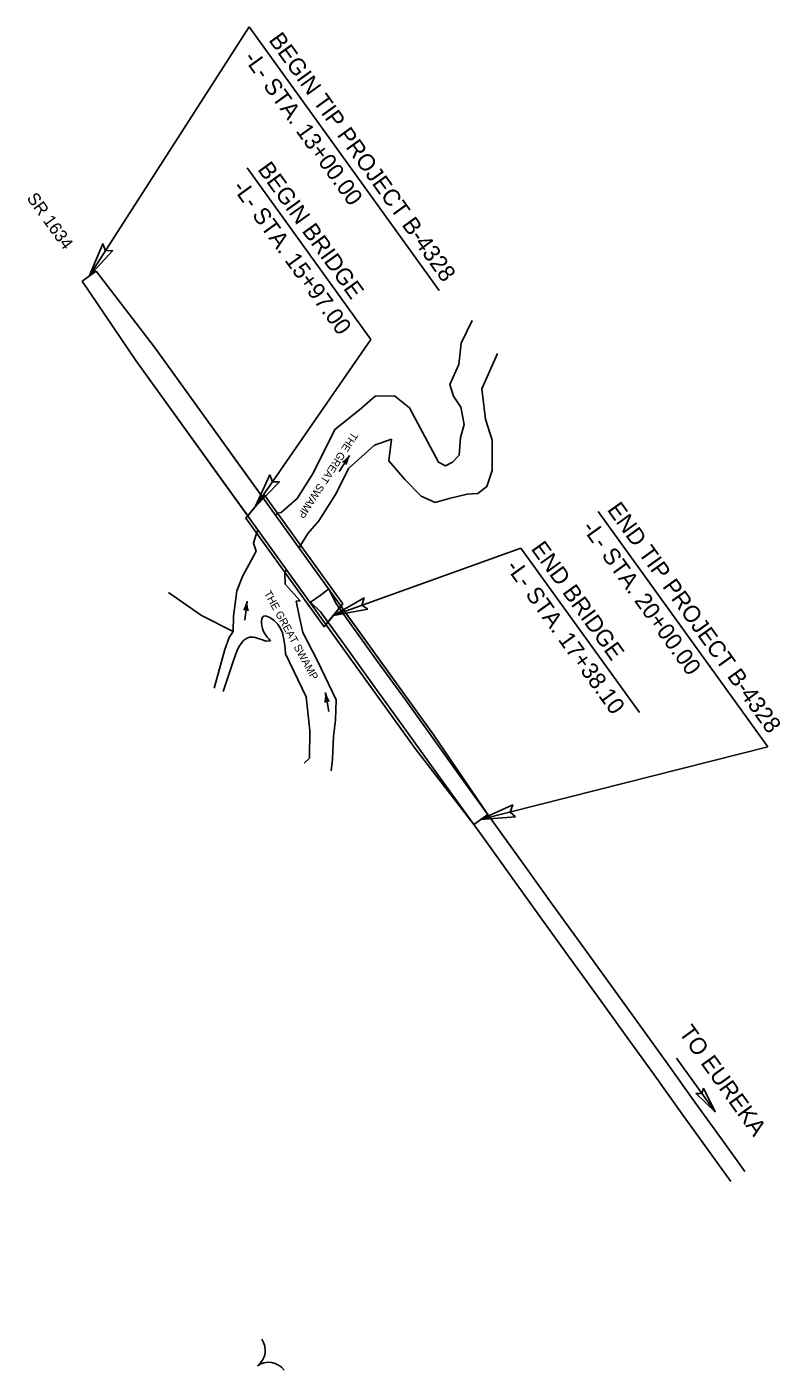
# Model space of a CAD drawing. Extents: x 1372027 to 1374286, y 553832 to 556743.
# Drawn here: x 1372027 to 1372814, y 553929 to 555333 of the extents above; entities that cross this region are included whole.
import ezdxf

# ---------------------------------------------------------------- set-up
doc = ezdxf.new("R2010")
doc.units = 0
for name, color, linetype in [('Default', 7, 'Continuous'), ('Old_Level_1', 7, 'Continuous'), ('Prop Dimension', 7, 'Continuous'), ('Prop EOT', 7, 'Continuous'), ('Prop Roadway Bridge', 7, 'Continuous'), ('Prop Shade Light', 7, 'Continuous'), ('Prop Shade Medium', 7, 'Continuous'), ('Prop Terminator CELL', 7, 'Continuous'), ('Sheet Plan Layout CELL', 7, 'Continuous')]:
    doc.layers.add(name, color=color, linetype=linetype)

# ---------------------------------------------------------------- blocks, each defined once
blk = doc.blocks.new('EXIST HYDRO RIVER FLOW ARROW')
at = {"layer": 'Default'}
for p, q in [((0.2, 0), (-0.2, 0)), ((0, 0.04575), (0.03775, 0.03)), ((0, 0), (0, 0)), ((0.03775, 0.03), (0.07725, 0.01725)), ((0.07725, 0.01725), (0.118, 0.00775)), ((0.118, 0.00775), (0.159, 0.0015)), ((0.159, 0.0015), (0.2, 0)), ((0.159, -0.0015), (0.2, 0)), ((0, -0.04575), (0.03775, -0.03)), ((0.03775, -0.03), (0.07725, -0.01725)), ((0.07725, -0.01725), (0.118, -0.00775)), ((0.118, -0.00775), (0.159, -0.0015))]:
    blk.add_line(p, q, dxfattribs=at)

msp = doc.modelspace()

# ---------------------------------------------------------------- linework, layer by layer
at = {"layer": 'Default'}
for p, q in [((1372411.1, 554947.6), (1372426.9, 554935)), ((1372405.3, 554879.8), (1372408, 554902.2)), ((1372342.5, 554745.7), (1372333.4, 554739)), ((1372342.5, 554745.7), (1372333.4, 554739)), ((1372350, 554730.9), (1372342.5, 554745.7)), ((1372350, 554730.9), (1372342.5, 554745.7)), ((1372333.4, 554739), (1372323.4, 554731.8)), ((1372333.4, 554739), (1372323.4, 554731.8)), ((1372323.4, 554731.8), (1372334, 554721.8)), ((1372323.4, 554731.8), (1372334, 554721.8)), ((1372364.3, 554710.7), (1372350, 554730.9)), ((1372334, 554721.8), (1372360.8, 554684.7)), ((1372393.4, 554670), (1372364.3, 554710.7)), ((1372281.6, 554691.5), (1372276.6, 554691.2)), ((1372360.8, 554684.7), (1372390.3, 554643.3)), ((1372422.6, 554629.7), (1372393.4, 554670)), ((1372232.1, 554638.4), (1372241.2, 554665.5)), ((1372390.3, 554643.3), (1372418.5, 554604.2)), ((1372451.6, 554589.3), (1372422.6, 554629.7)), ((1372418.5, 554604.2), (1372447.1, 554564.6)), ((1372481.4, 554548), (1372451.6, 554589.3)), ((1372447.1, 554564.6), (1372476, 554524.4)), ((1372511.4, 554506.2), (1372481.4, 554548)), ((1372476, 554524.4), (1372505.2, 554483.9)), ((1372547.2, 554456.4), (1372511.4, 554506.2)), ((1372505.2, 554483.9), (1372535.1, 554442.5)), ((1372576.9, 554415.2), (1372547.2, 554456.4)), ((1372535.1, 554442.5), (1372564.3, 554401.7)), ((1372607.3, 554372.8), (1372576.9, 554415.2)), ((1372564.3, 554401.7), (1372593.8, 554360.6)), ((1372593.8, 554360.6), (1372623.5, 554320)), ((1372637.5, 554331.3), (1372607.3, 554372.8)), ((1372623.5, 554320), (1372652.7, 554279.2)), ((1372667.3, 554289.9), (1372637.5, 554331.3)), ((1372652.7, 554279.2), (1372681.9, 554238.5)), ((1372696.8, 554248.7), (1372667.3, 554289.9)), ((1372725.2, 554209), (1372696.8, 554248.7)), ((1372705.9, 554255.2), (1372746.3, 554199)), ((1372681.9, 554238.5), (1372711.3, 554197.6)), ((1372753.7, 554169.5), (1372725.2, 554209)), ((1372711.3, 554197.6), (1372740.2, 554157.5)), ((1372777.3, 554136.7), (1372753.7, 554169.5)), ((1372740.2, 554157.5), (1372762.7, 554126.2))]:
    msp.add_line(p, q, dxfattribs=at)
for points in [[(1372426.9, 554935), (1372457.3, 554878.1), (1372464.5, 554874.6), (1372471.9, 554878.3), (1372478.9, 554885.6), (1372480.4, 554904.2), (1372484.1, 554917.5), (1372480.5, 554935.9), (1372472.8, 554947.4), (1372469, 554959.4), (1372478.6, 554980.3), (1372480.9, 555002.8), (1372492.6, 555026.4)], [(1372405.3, 554879.8), (1372422, 554860.1), (1372439.1, 554842.8), (1372453.7, 554836.1), (1372468.4, 554840.4), (1372487.3, 554844.9), (1372498.2, 554845.6), (1372507.9, 554852.8), (1372513.4, 554869.7), (1372513.2, 554901.2), (1372506.2, 554923.2), (1372502.6, 554955.1), (1372518.9, 554991.8)], [(1372411.1, 554947.6), (1372391.2, 554947.4), (1372374.6, 554933), (1372348.8, 554912.5), (1372326.3, 554866.8), (1372309.4, 554840.4), (1372292.8, 554825.8), (1372289.1, 554825.1), (1372287.4, 554823.2)], [(1372408, 554902.2), (1372390.2, 554896.1), (1372363.5, 554872.1), (1372349.5, 554844.4), (1372332.2, 554816.9), (1372320.5, 554803.8), (1372312.9, 554791.2), (1372312, 554789.3)], [(1372269, 554807.1), (1372267.6, 554806), (1372264, 554793.7), (1372266.5, 554785.1), (1372252.5, 554758.7), (1372246.3, 554743.6), (1372243, 554717.3), (1372242.5, 554701.2), (1372238.6, 554694.8), (1372233.8, 554682.5), (1372222.6, 554641.8)], [(1372298.5, 554765.9), (1372296.5, 554762.7), (1372297, 554750.8), (1372312.6, 554733.4), (1372308.5, 554732.9), (1372311.5, 554717.6), (1372315.3, 554700.2), (1372330.4, 554671.1), (1372350.2, 554629.6), (1372349.6, 554608.9), (1372347.5, 554591.5), (1372346.5, 554567.7), (1372345.2, 554555.5)], [(1372242.5, 554701.2), (1372209.5, 554717.9), (1372175, 554741.9)], [(1372297.4, 554677.8), (1372318.9, 554632.9), (1372322.6, 554597.6), (1372322.5, 554568.9), (1372316.7, 554563.6)]]:
    msp.add_lwpolyline(points, dxfattribs=at)
for points in [[(1372281.6, 554691.5), (1372272.3, 554709.9), (1372274.6, 554717.2), (1372280.9, 554715.8), (1372297.4, 554677.8)], [(1372241.2, 554665.5), (1372259.8, 554695.1), (1372276.6, 554691.2)]]:
    msp.add_spline(points, degree=3, dxfattribs=at)
at = {"layer": 'Prop Dimension'}
for p, q in [((1372092.2, 555072.7), (1372259.2, 555333.4)), ((1372259.2, 555333.4), (1372457.8, 555057.6)), ((1372257.1, 555185.9), (1372386.4, 555006.4)), ((1372099.5, 555077.9), (1372084.9, 555067.5)), ((1372265.7, 554831.6), (1372386.4, 555006.4)), ((1372624.2, 554826.7), (1372801.5, 554580.5)), ((1372543.3, 554788.5), (1372347.5, 554718)), ((1372543.3, 554788.5), (1372667.3, 554616.4)), ((1372801.5, 554580.5), (1372501.3, 554504.7)), ((1372494, 554499.4), (1372508.7, 554510))]:
    msp.add_line(p, q, dxfattribs=at)
at = {"layer": 'Prop EOT'}
for p, q in [((1372099.4, 555077.9), (1372084.9, 555067.5)), ((1372099.4, 555077.9), (1372160.3, 554998.5)), ((1372084.9, 555067.5), (1372140.8, 554984.5)), ((1372160.3, 554998.5), (1372452.4, 554592.7)), ((1372140.8, 554984.5), (1372433, 554578.7)), ((1372452.4, 554592.7), (1372508.7, 554510)), ((1372433, 554578.7), (1372494, 554499.4)), ((1372508.7, 554510), (1372494, 554499.4))]:
    msp.add_line(p, q, dxfattribs=at)
at = {"layer": 'Prop Roadway Bridge'}
for p, q in [((1372275.5, 554843.6), (1372255.9, 554819.7)), ((1372275.5, 554843.6), (1372357.2, 554730)), ((1372255.9, 554819.7), (1372337.7, 554706.1)), ((1372357.2, 554730), (1372337.7, 554706.1))]:
    msp.add_line(p, q, dxfattribs=at)
for centre, start, end in [((1372256.2, 553949.6), 305.7621, 35.7621), ((1372279.6, 553917.1), 35.7621, 125.7621)]:
    msp.add_arc(centre, 20, start, end, dxfattribs=at)
at = {"layer": 'Prop Shade Light'}
msp.add_lwpolyline([(1372347.5, 554718), (1372357.2, 554730), (1372275.5, 554843.6), (1372265.7, 554831.6), (1372265.7, 554831.6), (1372255.9, 554819.7), (1372337.7, 554706.1), (1372347.5, 554718)], close=True, dxfattribs=at)
at = {"layer": 'Prop Shade Medium'}
for points in [[(1372257.8, 554822), (1372273.5, 554841.2), (1372160.3, 554998.5), (1372099.4, 555077.9), (1372084.9, 555067.5), (1372140.8, 554984.5)], [(1372355.3, 554727.6), (1372339.6, 554708.4), (1372433, 554578.7), (1372494, 554499.4), (1372508.7, 554510), (1372452.4, 554592.7)]]:
    msp.add_lwpolyline(points, close=True, dxfattribs=at)
at = {"layer": 'Prop Terminator CELL'}
for points in [[(1372116.8, 555099.7), (1372092.2, 555072.7), (1372106.3, 555106.6), (1372109.2, 555099.3)], [(1372291.2, 554857.7), (1372265.7, 554831.6), (1372281, 554865), (1372283.6, 554857.6)], [(1372383.4, 554724.4), (1372347.5, 554718), (1372379.4, 554736.3), (1372377.2, 554728.7)], [(1372537.8, 554507.5), (1372501.3, 554504.7), (1372534.9, 554519.8), (1372532, 554512.4)], [(1372734.3, 554223.6), (1372746.3, 554199), (1372726.5, 554218.2), (1372732.5, 554218.2)]]:
    msp.add_lwpolyline(points, close=True, dxfattribs=at)

# ---------------------------------------------------------------- block references
at = {"layer": 'Default'}
for p, xscale, yscale, rotation in [((1372358.8, 554876.9), 50, 49.99999999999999, 57.03050123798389), ((1372256, 554723.1), 49.99999999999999, 50, 83.53419069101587), ((1372340.8, 554627.5), 49.99999999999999, 49.999999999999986, 100.44346250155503)]:
    msp.add_blockref('EXIST HYDRO RIVER FLOW ARROW', p, dxfattribs=dict(at, xscale=xscale, yscale=yscale, rotation=rotation))

# ---------------------------------------------------------------- texts
at = {"layer": 'Old_Level_1'}
for rotation, p in [(236.7647, (1372366.9, 554910.4)), (298.8415, (1372274.6, 554741.3))]:
    msp.add_text('THE GREAT SWAMP', height=8, rotation=rotation, dxfattribs=at).set_placement(p)
at = {"layer": 'Prop Dimension'}
for s, height, p in [('SR 1634', 13, (1372026.3, 555154.3)), ('TO EUREKA ', 17.5, (1372707.8, 554281.7))]:
    msp.add_text(s, height=height, rotation=305.7621, dxfattribs=at).set_placement(p)
at = {"layer": 'Sheet Plan Layout CELL'}
for s, p in [('BEGIN TIP PROJECT B-4328', (1372279.1, 555319.6)), ('-L- STA. 13+00.00', (1372252.8, 555300.6)), ('BEGIN BRIDGE', (1372267.5, 555184.4)), ('-L- STA. 15+97.00', (1372241.1, 555165.4)), ('END TIP PROJECT B-4328', (1372632.9, 554828.5)), ('-L- STA. 20+00.00', (1372606.5, 554809.5)), ('END BRIDGE', (1372553.3, 554787.6)), ('-L- STA. 17+38.10', (1372526.9, 554768.6))]:
    msp.add_text(s, height=17.5, rotation=305.7621, dxfattribs=at).set_placement(p)

doc.saveas('drawing.dxf')
